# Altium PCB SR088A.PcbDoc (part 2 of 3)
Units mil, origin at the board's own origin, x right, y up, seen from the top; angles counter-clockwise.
Board outline 5010 x 3800 mil, 6 copper layers (Top Layer, Signal Layer 1, Signal Layer 2, Signal Layer 3, Signal Layer 4, Bottom Layer), stack 61.4 mil thick; 199 components, 82 nets, 478 pads, 1347 vias.
Unrouted connection lines stored in the file: 13.
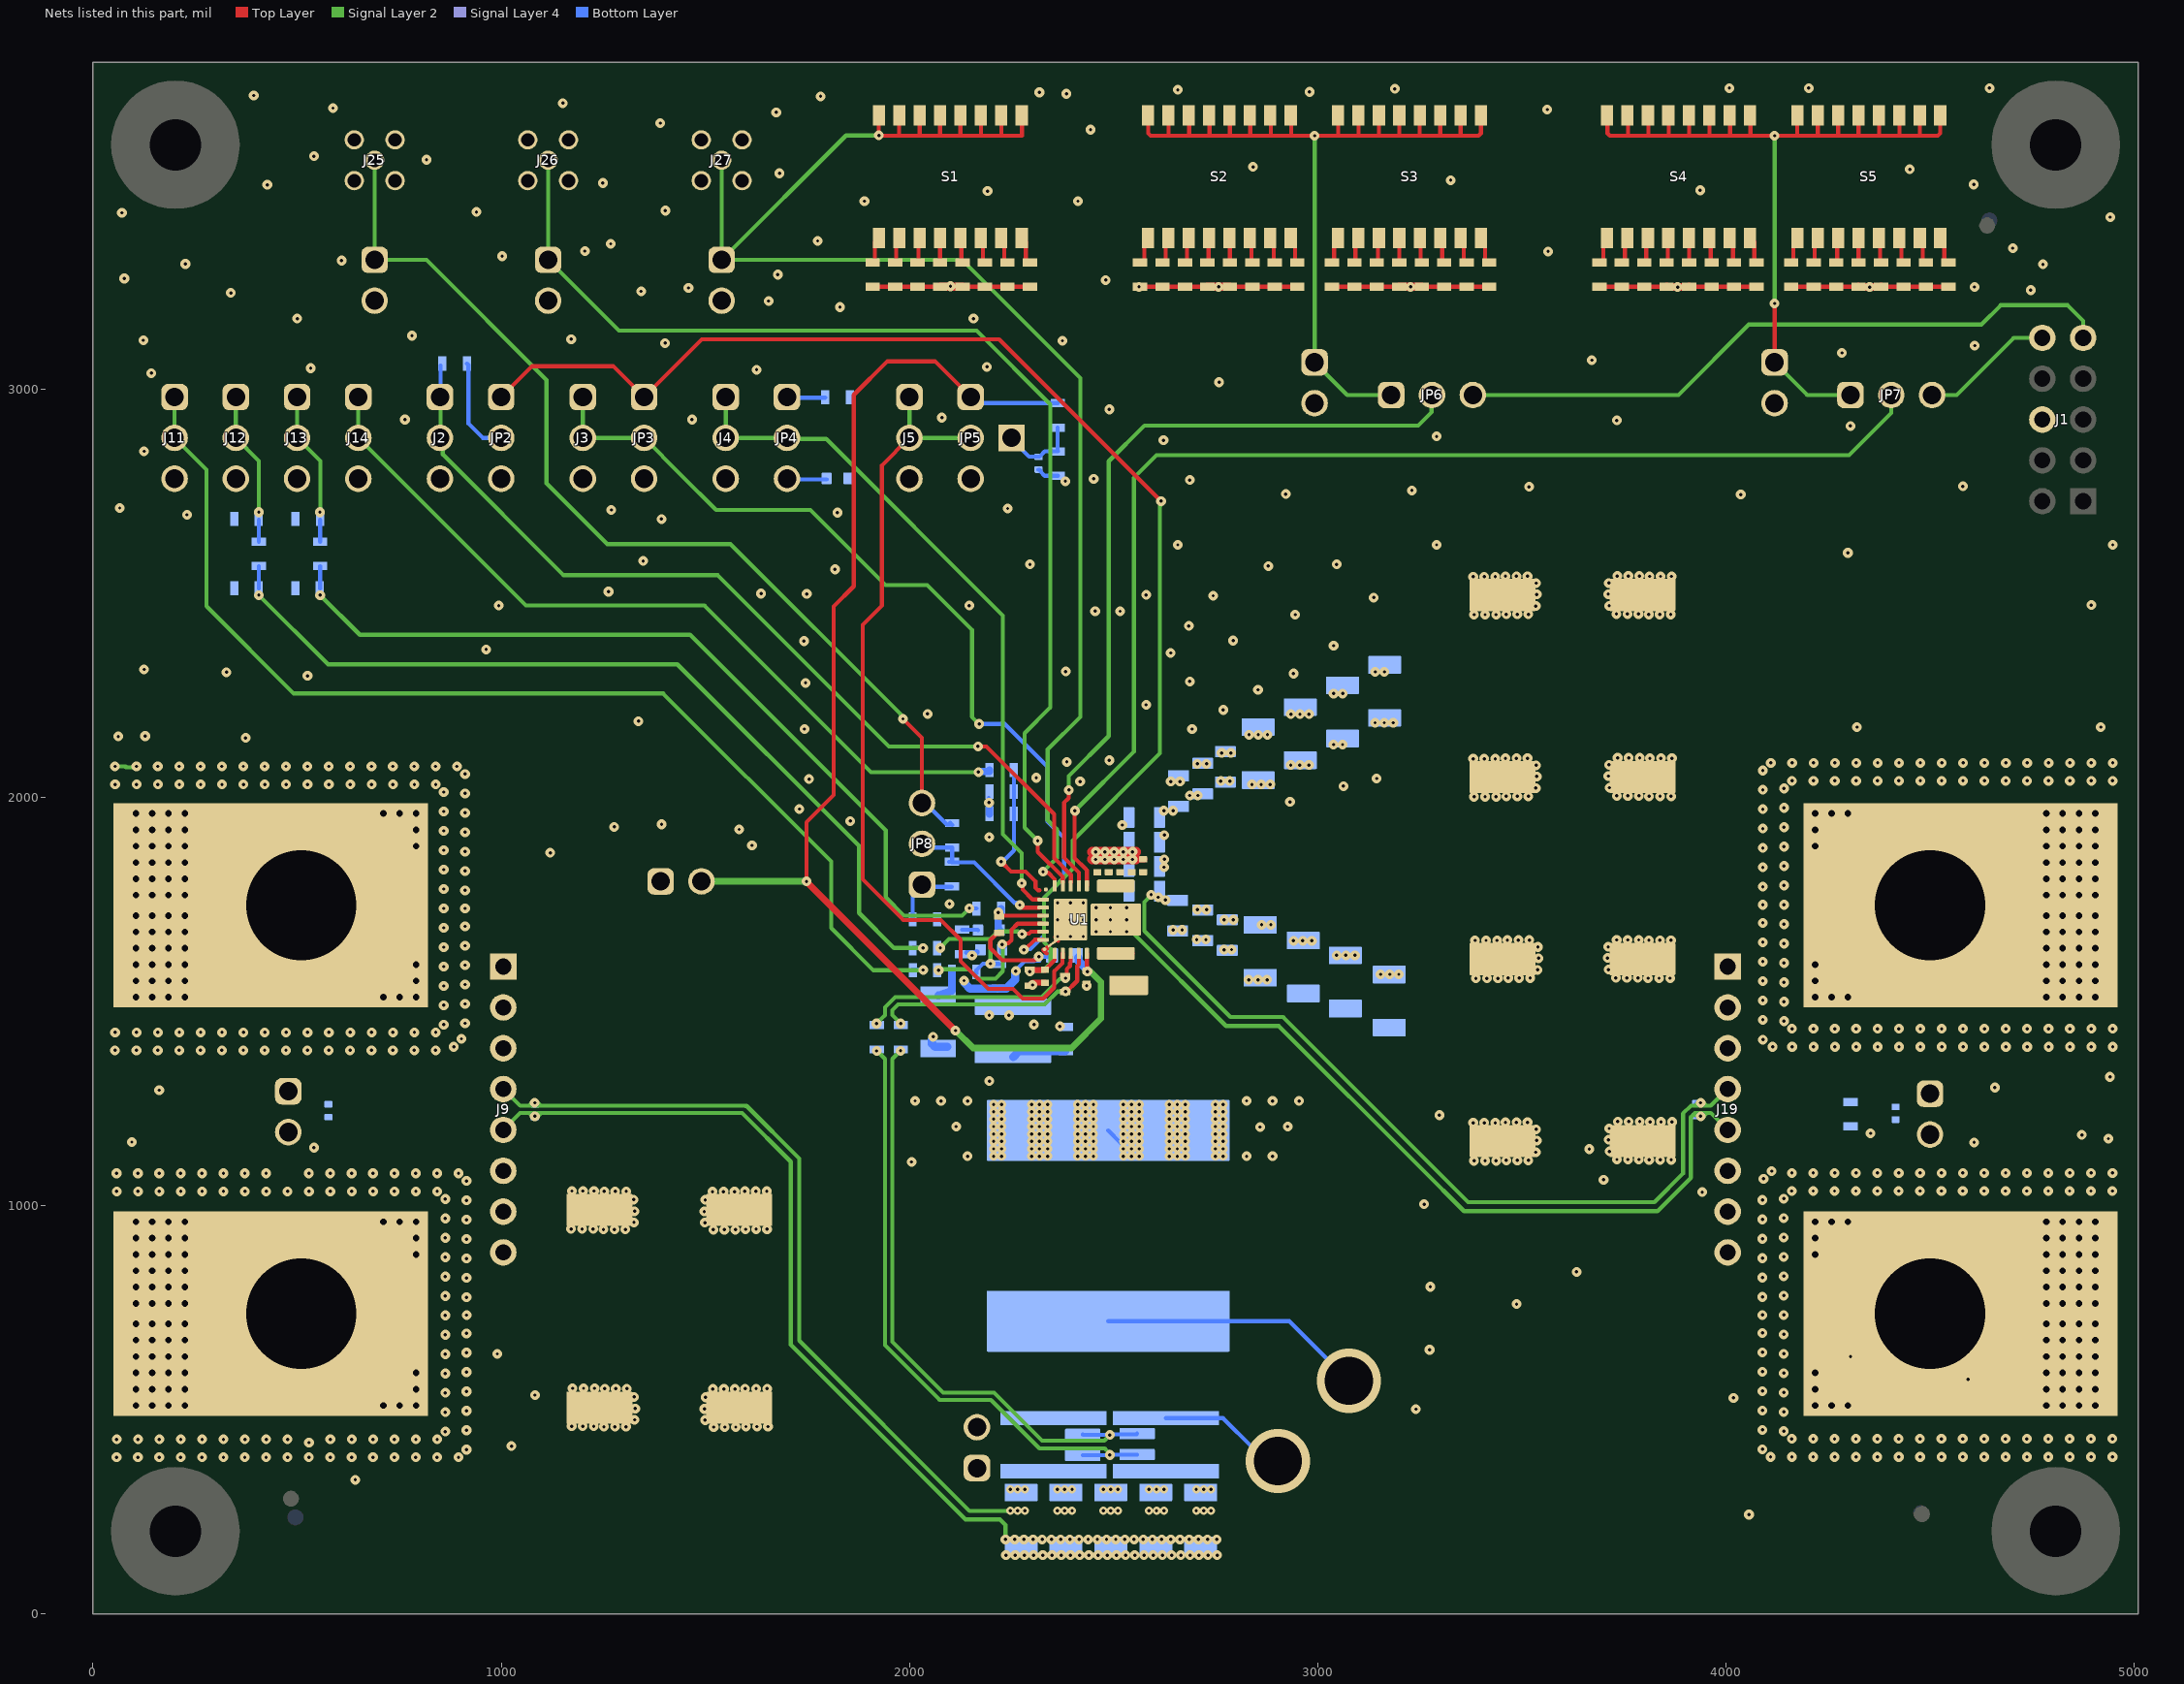
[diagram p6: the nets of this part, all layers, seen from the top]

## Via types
v1: diameter 24, hole 8, Top Layer to Bottom Layer, tented both sides, 935 vias

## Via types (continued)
v2: diameter 32, hole 16, Top Layer to Bottom Layer, 232 vias
v3: diameter 22, hole 8, Top Layer to Bottom Layer, tented both sides, 128 vias
v4: diameter 20, hole 8, Top Layer to Bottom Layer, tented both sides, 30 vias
v5: diameter 19.68, hole 7.87, Top Layer to Bottom Layer, tented both sides, 18 vias
v6: diameter 157.48, hole 118.11, Top Layer to Bottom Layer, 2 vias
v7: diameter 150, hole 125.98, Top Layer to Bottom Layer, 2 vias

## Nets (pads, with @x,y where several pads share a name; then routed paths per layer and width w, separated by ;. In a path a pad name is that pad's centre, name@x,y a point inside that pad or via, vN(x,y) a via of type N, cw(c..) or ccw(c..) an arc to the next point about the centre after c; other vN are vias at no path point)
AGND: C1.2 C2.2 C6.1 C7.1 C8.2 C10.2 C50.1 C51.1 C52.2 C53.2 C54.2 C55.2 J1.6 J2.3 J3.3 J4.3 J5.3 J6.2 J7.2 J11.3 J12.3 J13.3 J14.3 J15.2 J16.2 J17.2 J25.2 J25.3 J25.4 J25.5 J26.2 J26.3 J26.4 J26.5 J27.2 J27.3 J27.4 J27.5 JP2.3 JP3.3 JP5.3 NT1.2 R7.1 R9.1 R11.1 R13.2 R15.2 R16.1 R17.1 R18.1 R19.2 R20.1 R21.1 R22.1 R23.2 R24.2 R25.1 R26.2 R27.1 R28.2 R29.1 R30.1 R31.1 R32.1 R33.1 R34.1 R35.2 R36.1 R37.1 R38.1 R39.2 R40.2 R41.1 R42.2 R43.1 R44.2 R45.1 R46.1 R47.1 R48.1 R49.1 R50.1 R51.2 R52.1 R53.1 R54.1 R55.2 R60.1 U1.1 | length 2626.8
  Top Layer w6: U1.1@2333.63,1629.09 NT1.2@2345.16,1637.81
  Top Layer w10: R16.1@1910,3250 R17.1@1965,3250 R18.1@2020,3250 R19.2@2075,3250 ; R20.1@2130,3250 R21.1@2185,3250 R22.1@2240,3250 R23.2@2295,3250 ; C10.2@2220.47,1664.74 2212.86,1664.74 2198.39,1650.27 2198.39,1630.08 2227.84,1600.62 2307.92,1600.62 v1(2316.8,1609.5) ; U1.1@2334.25,1628.49 2338.2,1632.45 ; 2336.1,1628.15 2336.18,1628.23 ; 2336.26,1617.32 U1.1@2327.56,1626.02 ; R24.2@2565,3250 R25.1@2620,3250 R26.2@2675,3250 R27.1@2730,3250 ; R28.2@2785,3250 R29.1@2840,3250 R30.1@2895,3250 R31.1@2950,3250 ; R32.1@3035,3250 R33.1@3090,3250 R34.1@3145,3250 R35.2@3200,3250 ; R36.1@3255,3250 R37.1@3310,3250 R38.1@3365,3250 R39.2@3420,3250 ; R40.2@3690,3250 R41.1@3745,3250 R42.2@3800,3250 R43.1@3855,3250 ; R44.2@3910,3250 R45.1@3965,3250 R46.1@4020,3250 R47.1@4075,3250 ; R48.1@4160,3250 R49.1@4215,3250 R50.1@4270,3250 R51.2@4325,3250 ; R52.1@4380,3250 R53.1@4435,3250 R54.1@4490,3250 R55.2@4545,3250 ; U1.1@2327.56,1626.02 2327.91,1626.11 2329.13,1626.42 U1.1@2327.56,1626.02
  Top Layer w19.5: R19.2@2075,3250 R20.1@2130,3250 ; R27.1@2730,3250 R28.2@2785,3250 ; R35.2@3200,3250 R36.1@3255,3250 ; R43.1@3855,3250 3855.25,3249.75 3881.35,3249.75 v1(3881.79,3249.31) 3882.24,3249.75 3909.75,3249.75 R44.2@3910,3250 ; R51.2@4325,3250 4325.25,3249.75 4351.71,3249.75 v1(4352.21,3249.26) 4352.7,3249.75 4379.75,3249.75 R52.1@4380,3250
  Bottom Layer w10: v1@2152.75,1609.7 2153.16,1609.3 2156.61,1609.3 C6.1@2164.46,1617.14 ; R7.1@2194.26,1997.6 2194.26,1987.48 v1(2194.95,1986.79) ; v1(2260.64,1574.06) 2260.64,1576.87 2281.82,1598.06 2305.36,1598.06 2307.19,1599.89 v1@2318.66,1599.89 ; 2303.4,1599.89 2313.01,1609.5 2346.18,1609.5 C1.2@2349.21,1612.53 ; C51.1@2316.23,2802.09 2318.2,2802.09 2321.08,2799.22 2321.08,2797.25 2331.32,2787.01 R15.2@2363.46,2787.01
  Bottom Layer w12: R9.1@2139.67,1619.58 C6.1@2165.96,1619.58
  Bottom Layer w14: v1@2152.75,1609.7 C6.1@2164.46,1621.24
  Bottom Layer w18: C7.1@2195.76,1958.82 v1@2195.76,1985.98
  Bottom Layer w20: C8.2@2055.25,1405.88 2055.25,1396.06 2062.95,1388.36 C8.2@2092.79,1388.36 ; v1(2133.75,1550.48) 2133.75,1549.4 2135.92,1547.23 2135.92,1543.57 2148.43,1531.06 R60.1@2211.91,1531.06 ; R60.1@2219.41,1531.06 2237.5,1531.06 2258.76,1552.32 2258.76,1569.36 2259.87,1570.46 2259.87,1573.29 v1(2260.64,1574.06)
  other v1: 2057.97,1413.36 2305.04,1443.21 2434.18,1538.24 2153.38,1612.48 2098.18,1738.59 2195.63,1902.13 1582.79,1921.11 1392.85,1933.57 1855.21,1941.54 1730.3,1970.97 2418.14,2038.2 1754.21,2044.11 2310.81,2047.43 2385.39,2086.44 2489.54,2090.34 1742.85,2166.88 1336.32,2186.01 2044.36,2203.82 2579.72,2226.19 1745.44,2279.86 525.61,2297.08 2382.73,2307.83 2639.98,2353.15 962.99,2361.97 1741.62,2382.44 2516.15,2455.43 2454.84,2455.66 993.91,2469.25 2146.6,2469.25 2579.72,2495.39 1748.4,2497.66 1636.7,2498.66 1263,2503.31 1817.55,2557.97 2295.11,2570.15 1347.93,2578.51 2657.26,2618.11 1392.49,2681.16 230.3,2691.59 1823.7,2696.85 1269.88,2703.43 2240.63,2707.05 65.55,2708.16 4036.47,2741.1 2921.88,2742.37 3230.71,2751.27 3517.94,2760.17 4580.42,2761.44 2381.97,2773.7 2686.76,2776.69 2451.45,2779.77 125.12,2847.16 2622.44,2874.18 3291.47,2883.63 4305,2909.18 3732.72,2922.84 764.28,2924.99 1467.42,2924.99 2079.6,2929.73 2489.64,2949.82 2758.7,3016.38 142.93,3038.47 1625.52,3047.04 533.34,3050.76 2189.98,3053.97 3671.72,3070.27 4284.3,3088.06 4609.65,3105.85 1401.65,3112.1 2374.65,3117.83 123.25,3118.93 1171.53,3121.65 781.44,3130.38 500.31,3172.19 2156.94,3172.26 1829.68,3200.4 1655,3215.26 337.64,3234.97 1342.67,3239.07 4746.74,3241.82 1458.71,3247.28 2562.5,3250 2757.5,3250 3227.5,3250 4608.99,3249.75 2100.5,3251.48 2480.68,3266.56 76.79,3270.48 1677.61,3279.91 4776.66,3305.22 226.49,3305.96 608.91,3314.21 1002.36,3325.02 3564.4,3336.5 1205,3337.42 4702.69,3344.7 1268.11,3355.16 1775.34,3362.39 4941.3,3420.52 70.77,3431.37 939.26,3433.46 1402.24,3436.6 1889.76,3459.67 2412.84,3459.67 2191.31,3484.5 3936.79,3486.41 427.17,3499.83 4607.1,3500.73 1249.01,3504.17 3325.68,3511.23 1681.73,3528 4450.5,3537.97 2841.57,3543.7 816.93,3561.24 541.34,3569.83 2443.54,3635 1389.56,3651 1673.61,3677.47 3562.49,3684.06 588.04,3687.62 1150.94,3699.91 1782.35,3716.59 393.7,3718.68 2384.49,3722.84 2318.48,3726.43 2979.88,3727.56 2657.48,3732.45 3188.98,3735.01 4008.36,3736.69 4202.76,3736.69 4645.67,3736.69
ATRK: JP8.2 R58.1 R59.2 U1.17 | length 381.7
  Top Layer w10: v1(2270.2,1735.78) 2276.46,1729.53 U1.17@2318.62,1729.53
  Bottom Layer w10: JP8.2@2030.69,1885.7 2039.92,1876.46 R59.2@2104.86,1876.46 2104.86,1841.41 R58.1@2096.99,1841.41 ; R58.1@2103.67,1840.21 2158.49,1840.21 2257.47,1741.23 2260.97,1741.23 2266.42,1735.78 v1(2270.2,1735.78)
ATRK_EXT: J15.1 J25.1 JP8.3 R59.1 | length 2499.2
  Top Layer w10: v1(1984.31,2191.81) 2030.69,2145.43 JP8.3@2030.69,1985.7
  Signal Layer 2 w10: J15.1@690,3295 J25.1@690,3560 ; J15.1@690,3316 816.75,3316 1111.02,3021.73 1111.02,2768.6 1259.71,2619.91 1561.67,2619.91 1977.95,2203.63 1977.95,2201.96 1984.31,2195.6 v1(1984.31,2191.81)
  Bottom Layer w10: JP8.3@2030.69,1985.7 2038.71,1985.7 2091.66,1932.75 R59.1@2099.16,1932.75 ; R59.1@2099.92,1936.9 R59.1@2104.92,1931.9
BIAS: C1.1 C2.1 JP1.2 JP5.1 R14.2 U1.6 | length 3211.5
  Top Layer w10: v1@1747.8,1793.21 1747.8,1938.45 1814.55,2005.19 1814.55,2467.32 1863.62,2516.4 1863.62,2985.34 1945.86,3067.58 2062.42,3067.58 JP5.1@2150,2980 ; U1.6@2434.68,1617.32 2434.68,1582.08 2437.56,1579.21 C2.1@2437.85,1579.21
  Top Layer w16: v1@1747.8,1793.21 v1(2112.61,1428.4) ; C2.1@2437.39,1576.42 C2.1@2437.85,1576.89
  Signal Layer 2 w16: JP1.2@1490.54,1793.81 v1@1748.4,1793.81 ; v1@2112.89,1428.69 2155.86,1385.72 2397.07,1385.72 2469.06,1457.71 2469.06,1547.33 2445.04,1571.36 2437.35,1571.36 v1(2435.82,1572.89)
  Bottom Layer w10: JP5.1@2150,2980 2164.84,2965.16 R14.2@2363.46,2965.16
  Bottom Layer w20: C1.1@2412.74,1607.07 2414.99,1604.81 2414.99,1597.48 2435.05,1577.42 2435.05,1573.65 v1(2435.82,1572.89)
  other v1: 1747.8,1793.81
CFG1: JP6.2 U1.11 | length 1983.3
  Top Layer w10: v1@2390.34,2014.74 2390.34,1997.77 2378.7,1986.13 2378.7,1851.96 2415,1815.66 U1.11@2415,1782.68
  Signal Layer 2 w10: v1@2390.34,2014.74 2390.34,2051.75 2488.13,2149.54 2488.13,2822.66 2575.77,2910.3 3246.03,2910.3 3279.11,2943.38 3279.11,2984.11 JP6.2@3280,2985
  other v1: 2390.55,2017.46
CFG2: JP7.2 U1.10 | length 3057.6
  Top Layer w10: v1@2404.73,1966.86 2404.73,1851.2 2432.87,1823.06 2434.68,1820.5 U1.10@2434.68,1782.68
  Signal Layer 2 w10: v1(2405.19,1966.86) 2549.72,2111.39 2549.72,2782.15 2605.1,2837.52 4301.83,2837.52 4405,2940.69 JP7.2@4405,3005.77
COMP: C9.2 C10.1 R56.1 U1.18 | length 168.8
  Top Layer w10: C10.1@2218.85,1708.24 C10.1@2219.86,1707.24 ; C10.1@2226.86,1709.74 2232.61,1709.74 2232.72,1709.84 U1.18@2327.4,1709.84
  Top Layer w16: v1(2217.85,1717.76) 2218.85,1716.76 C10.1@2218.85,1708.24
  Bottom Layer w18: R56.1@2217.52,1717.43 2217.52,1677.85 C9.2@2221.03,1674.34 ; R56.1@2220.62,1717.76 2220.62,1718.91 2223.11,1718.91 2224.11,1719.91 R56.1@2224.11,1727.2
COMP_J: C53.1 R56.2 R62.1 | length 2091.1
  Signal Layer 2 w10: v1(556.59,2494.96) 653.82,2397.73 1462.52,2397.73 1941.87,1918.39 1941.87,1754.37 1986.6,1709.64 2128.72,1709.64 v1(2146.78,1727.7)
  Bottom Layer w10: R62.1@556.33,2565.95 556.4,2565.87 C53.1@556.4,2511.47 ; v1(2146.78,1727.7) 2163.6,1727.7 R56.2@2164.11,1727.2
CSA: C5.2 R5.1 U1.4 | length 580.2
  Top Layer w10: C5.2@2381.19,1562.43 2383.06,1562.43 2385.56,1564.93 2385.56,1578.78 2393.08,1586.31 2393.08,1593.65 2395.24,1595.81 U1.4@2395.24,1608.54
  Signal Layer 2 w10: v1(1919.57,1445.5) 1940.06,1465.99 1940.06,1485.28 1965.15,1510.36 2323.74,1510.36 2367.34,1553.96 2375.66,1553.96 2382.13,1560.43 v1@2382.13,1562.7
  Bottom Layer w10: R5.1@1919.57,1442.03 v1(1919.57,1445.5)
  other v1: 2382.13,1556.64
CSB: C5.1 R6.1 U1.5 | length 590
  Top Layer w10: C5.1@2382.29,1521.34 C5.1@2383.5,1522.54 ; C5.1@2383.31,1523.6 2383,1523.03 C5.1@2383.5,1522.54 ; C5.1@2383.71,1522.33 C5.1@2383.5,1522.54 ; U1.5@2414.92,1608.54 2414.92,1590.21 2410.96,1586.25 2410.96,1573.65 ccw(c2435.82,1572.89) 2410.96,1572.13 2410.96,1550 C5.1@2383.5,1522.54
  Signal Layer 2 w10: v1(1978.47,1445.5) 1978.47,1445.83 1957.94,1466.37 1957.94,1477.87 1972.55,1492.49 2331.14,1492.49 2362.72,1524.06 v1(2382.46,1524.06)
  Bottom Layer w10: R6.1@1979.3,1442.03 R6.1@1979.3,1445.08
DIP1: J6.1 JP6.1 S2.9 S2.10 S2.11 S2.12 S2.13 S2.14 S2.15 S2.16 S3.9 S3.10 S3.11 S3.12 S3.13 S3.14 S3.15 S3.16 | length 2383.1
  Top Layer w10: S2.16@2585,3670 2585,3625.86 2590.86,3620 v1(2992.5,3620) 3394.14,3620 3400,3625.86 S3.9@3400,3670 ; 2635,3620.79 2635,3670 S2.15@2635,3670.79 ; 2685,3620.79 2685,3670 S2.14@2685,3670.79 ; 2735,3621.79 2735,3670 S2.13@2735,3671.57 ; 2785,3621.57 2785,3670 S2.12@2785,3671.57 ; 2835,3620.79 2835,3670 S2.11@2835,3671.57 ; 2885,3621.79 2885,3670 S2.10@2885,3671.57 ; 2935,3621.57 2935,3670 S2.9@2935,3671.57 ; 3050,3620.79 S3.16@3050,3670 S3.16@3050,3670.79 ; 3100,3620.79 S3.15@3100,3670 S3.15@3100,3670.79 ; 3150,3621.79 S3.14@3150,3670 S3.14@3150,3671.57 ; 3200,3621.57 S3.13@3200,3670 S3.13@3200,3671.57 ; 3250,3620.79 S3.12@3250,3670 S3.12@3250,3671.57 ; 3300,3621.79 S3.11@3300,3670 S3.11@3300,3671.57 ; 3350,3621.57 S3.10@3350,3670 S3.10@3350,3671.57
  Signal Layer 2 w10: J6.1@2989.98,3067.45 3072.43,2985 JP6.1@3180,2985 ; J6.1@2992.5,3069.98 v1(2992.5,3620)
DIP2: J7.1 JP7.1 S4.9 S4.10 S4.11 S4.12 S4.13 S4.14 S4.15 S4.16 S5.9 S5.10 S5.11 S5.12 S5.13 S5.14 S5.15 S5.16 | length 2383
  Top Layer w10: S4.16@3710,3670 3710,3625.86 3715.86,3620 3760,3620 3810,3620 3860,3620 3910,3620 3960,3620 4010,3620 4119.13,3620 v1(4119.22,3619.91) 4119.32,3620 4225,3620 4275,3620 4325,3620 4375,3620 4425,3620 4475,3620 4519.14,3620 4525,3625.86 S5.9@4525,3670 ; 3760,3620.79 3760,3670 S4.15@3760,3670.79 ; 3810,3620.79 3810,3670 S4.14@3810,3670.79 ; 3860,3621.79 3860,3670 S4.13@3860,3671.57 ; 3910,3621.57 3910,3670 S4.12@3910,3671.57 ; 3960,3620.79 3960,3670 S4.11@3960,3671.57 ; 4010,3621.79 4010,3670 S4.10@4010,3671.57 ; 4060,3621.57 4060,3670 S4.9@4060,3671.57 ; J7.1@4119.22,3085 v1(4119.22,3209.39) ; 4175,3620.79 S5.16@4175,3670 S5.16@4175,3670.79 ; 4225,3620.79 S5.15@4225,3670 S5.15@4225,3670.79 ; 4275,3621.79 S5.14@4275,3670 S5.14@4275,3671.57 ; 4325,3621.57 S5.13@4325,3670 S5.13@4325,3671.57 ; 4375,3620.79 S5.12@4375,3670 S5.12@4375,3671.57 ; 4425,3621.79 S5.11@4425,3670 S5.11@4425,3671.57 ; 4475,3621.57 S5.10@4475,3670 S5.10@4475,3671.57
  Signal Layer 2 w10: J7.1@4106.6,3077.62 4199.22,2985 JP7.1@4305,2985 ; v1(4119.22,3209.39) v1(4119.22,3619.91)
  Signal Layer 4 w10: v1@4117.5,3211.11 v1(4119.22,3209.39)
DLY: J4.1 J4.2 JP4.2 U1.16 | length 1699.4
  Top Layer w10: v1@2273.71,1786.75 2277.44,1783.02 2277.44,1773.65 2301.8,1749.29 U1.16@2318.62,1749.29
  Signal Layer 2 w10: J4.1@1550,2980 J4.2@1550,2880 JP4.2@1700,2880 1702.71,2877.29 1796.16,2877.29 2228.64,2444.82 2228.64,1909.24 2275.03,1862.84 v1(2275.03,1789.42)
IMON: R8.2 R60.2 R61.1 U1.20 | length 395.4
  Top Layer w10: v1(2276,1664.61) 2277.16,1665.76 2293.04,1665.76 2297.67,1670.39 U1.20@2318.62,1670.39
  Signal Layer 2 w10: v1(2075.66,1630.83) 2097.25,1652.43 2198.39,1652.43 ; v1(2198.39,1592.27) 2198.39,1652.43 ; v1(2276,1664.61) 2272.22,1664.61 2265.5,1671.33 2217.29,1671.33 2198.39,1652.43
  Bottom Layer w10: R8.2@2163.79,1568.48 2163.79,1575.98 2180.08,1592.27 v1(2198.39,1592.27) 2198.99,1591.66 2218.8,1591.66 R60.2@2219.41,1591.06
IMON_J: C55.1 R61.2 R63.1 | length 2161.5
  Signal Layer 2 w10: v1(406.27,2494.96) 575.89,2325.34 1431.59,2325.34 1876.59,1880.34 1876.59,1716.13 1962.16,1630.55 v1(2033.41,1630.55)
  Bottom Layer w10: C55.1@406.4,2511.47 R63.1@406.4,2565.95 ; R61.2@2007.95,1630.21 2008.3,1630.55 v1(2033.41,1630.55)
L1: J8.2 L1.1 R1.2 R2.2 R3.2 R4.2 R6.2 | length 2385.6
  Signal Layer 2 w10: v1@1974.16,1375.25 1957.88,1358.97 1957.88,666.35 2082.47,541.76 2207.1,541.76 2324.62,424.24 2477.45,424.24 v1(2490.94,437.72)
  Bottom Layer w10: R6.2@1978.08,1380.88 R6.2@1978.08,1382.03 ; R2.2@2424.48,439.24 2425.24,438.48 2490.17,438.48 v1(2490.94,437.72) 2492.52,439.31 2556.1,439.31 R1.2@2557.69,440.9 ; L1.1@2487,716.54 2930.55,716.54 v6(3076.45,570.64) ; R3.2@2628.16,478.96 2768.22,478.96 v6@2842.31,404.87
  other v1: 1978.19,1378.75
  other v6: 2902.31,374.01
MODE: J3.1 J3.2 JP3.2 U1.21 | length 2267.2
  Top Layer w10: v1(2280.51,1626.42) 2282.47,1626.42 2306.83,1650.79 U1.21@2327.4,1650.79
  Signal Layer 2 w10: J3.1@1200,2980 J3.2@1200,2880 JP3.2@1350,2880 1440.72,2789.28 1526.57,2703.43 1757.62,2703.43 1941.36,2519.69 2043.29,2519.69 2153.16,2409.82 2153.16,2196.94 v1(2170.75,2179.34)
  Bottom Layer w10: v1(2170.75,2179.34) 2233.23,2179.34 2338.6,2073.97 2338.6,1940.31 2379.1,1899.81 2379.1,1803.19 2329.41,1753.5 2329.41,1661.29 2296.62,1628.5 2283.83,1628.5 v1@2281.13,1625.8
NetC8_1: C8.1 R8.1 | length 81.2
  Bottom Layer w19.5: C8.1@2070.78,1514.33 2103.93,1526.23 2103.93,1534.6 2103.99,1564.43 R8.1@2104,1572.18
NetC9_1: C9.1 R9.2 | length 39.4
  Bottom Layer w10: R9.2@2129.01,1675.62 2129.65,1674.98 2167.24,1674.98 C9.1@2167.88,1674.34
NetC20_2: C20.2 R10.2 | length 132.5
  Bottom Layer w20: R10.2@2254.19,1363.52 2268.05,1377.37 C20.2@2381,1377.37
NetC50_2: C50.2 JP4.3 | length 96.7
  Bottom Layer w10: JP4.3@1700.48,2778.26 C50.2@1797.2,2778.26
NetC51_2: C51.2 JP9.1 R14.1 R15.1 | length 196.8
  Bottom Layer w10: JP9.1@2248.52,2878.7 2293.25,2833.97 2318.58,2833.97 2321.08,2836.46 2321.08,2836.64 2331.45,2847.01 R15.1@2363.46,2847.01 ; R15.1@2363.13,2847.34 R14.1@2363.13,2905.16
NetC52_1: C52.1 J13.1 J13.2 R62.2 | length 359.1
  Signal Layer 2 w10: J13.1@500,2980 J13.2@500,2880 556.73,2823.27 556.73,2699.03 v1(555.77,2698.07)
  Bottom Layer w10: R62.2@556.33,2625.95 C52.1@556.33,2679.25
NetC54_1: C54.1 J12.1 J12.2 R63.2 | length 356.8
  Signal Layer 2 w10: J12.1@350,2980 J12.2@350,2880 406.45,2823.55 406.45,2700.09 v1@406.27,2699.91
  Bottom Layer w10: R63.2@406.4,2625.95 C54.1@406.4,2679.25
  other v1: 406.27,2698.07
NetJP2_2: JP2.2 R12.1 | length 243.4
  Bottom Layer w10: R12.1@916.15,3062.08 920,3058.22 920,2914.55 954.55,2880 JP2.2@1000,2880
NetJP4_1: JP4.1 R13.1 | length 93.7
  Bottom Layer w10: JP4.1@1700.48,2978.26 1792.77,2978.26 R13.1@1793.77,2979.26
NetJP8_1: JP8.1 R11.2 R58.2 | length 169.2
  Bottom Layer w10: R11.2@2007.95,1701.13 2007.95,1756.88 2030.69,1779.62 JP8.1@2030.69,1785.7 2036.18,1780.21 R58.2@2103.67,1780.21
NetR16_2: R16.2 S1.1 | length 66.3
  Top Layer w10: R16.2@1910,3310 1910.23,3310 1915.23,3315 1915.23,3360.23 S1.1@1925,3370
NetR17_2: R17.2 S1.2 | length 64.1
  Top Layer w10: R17.2@1965,3310 1965,3312.52 1967.48,3315 1967.48,3362.48 S1.2@1975,3370
NetR18_2: R18.2 S1.3 | length 62.1
  Top Layer w10: R18.2@2020,3310 2022.49,3312.49 2022.49,3367.49 S1.3@2025,3370
NetR19_1: R19.1 S1.4 | length 60
  Top Layer w10: R19.1@2075,3310 S1.4@2075,3370
NetR20_2: R20.2 S1.5 | length 62.1
  Top Layer w10: S1.5@2125,3370 2127.38,3367.62 2127.38,3312.62 R20.2@2130,3310
NetR21_2: R21.2 S1.6 | length 64.1
  Top Layer w10: S1.6@2175,3370 2180,3365 2180,3315 R21.2@2185,3310
NetR22_2: R22.2 S1.7 | length 67.7
  Top Layer w10: S1.7@2225,3370 2232.5,3362.5 2232.5,3315 2237.5,3310 R22.2@2240,3310
NetR23_1: R23.1 S1.8 | length 71.3
  Top Layer w10: S1.8@2275,3370 2284.91,3360.09 2284.91,3315 2289.91,3310 R23.1@2295,3310
NetR24_1: R24.1 S2.1 | length 71.3
  Top Layer w10: R24.1@2565,3310 2570.09,3310 2575.09,3315 2575.09,3360.09 S2.1@2585,3370
NetR25_2: R25.2 S2.2 | length 67.7
  Top Layer w10: R25.2@2620,3310 2622.5,3310 2627.5,3315 2627.5,3362.5 S2.2@2635,3370
NetR26_1: R26.1 S2.3 | length 64.1
  Top Layer w10: R26.1@2675,3310 2680,3315 2680,3365 S2.3@2685,3370
NetR27_2: R27.2 S2.4 | length 62.1
  Top Layer w10: R27.2@2730,3310 2732.62,3312.62 2732.62,3367.62 S2.4@2735,3370
NetR28_1: R28.1 S2.5 | length 60
  Top Layer w10: R28.1@2785,3310 S2.5@2785,3370
NetR29_2: R29.2 S2.6 | length 62.1
  Top Layer w10: S2.6@2835,3370 2837.51,3367.49 2837.51,3312.49 R29.2@2840,3310
NetR30_2: R30.2 S2.7 | length 64.1
  Top Layer w10: S2.7@2885,3370 2892.52,3362.48 2892.52,3315 2895,3312.52 R30.2@2895,3310
NetR31_2: R31.2 S2.8 | length 66.3
  Top Layer w10: S2.8@2935,3370 2944.77,3360.23 2944.77,3315 2949.77,3310 R31.2@2950,3310
NetR32_2: R32.2 S3.1 | length 66.3
  Top Layer w10: R32.2@3035,3310 3035.23,3310 3040.23,3315 3040.23,3360.23 S3.1@3050,3370
NetR33_2: R33.2 S3.2 | length 64.1
  Top Layer w10: R33.2@3090,3310 3090,3312.52 3092.48,3315 3092.48,3362.48 S3.2@3100,3370
NetR34_2: R34.2 S3.3 | length 62.1
  Top Layer w10: R34.2@3145,3310 3147.49,3312.49 3147.49,3367.49 S3.3@3150,3370
NetR35_1: R35.1 S3.4 | length 60
  Top Layer w10: R35.1@3200,3310 S3.4@3200,3370
NetR36_2: R36.2 S3.5 | length 62.1
  Top Layer w10: S3.5@3250,3370 3252.38,3367.62 3252.38,3312.62 R36.2@3255,3310
NetR37_2: R37.2 S3.6 | length 64.1
  Top Layer w10: S3.6@3300,3370 3305,3365 3305,3315 R37.2@3310,3310
NetR38_2: R38.2 S3.7 | length 67.7
  Top Layer w10: S3.7@3350,3370 3357.5,3362.5 3357.5,3315 3362.5,3310 R38.2@3365,3310
NetR39_1: R39.1 S3.8 | length 71.3
  Top Layer w10: S3.8@3400,3370 3409.91,3360.09 3409.91,3315 3414.91,3310 R39.1@3420,3310
NetR40_1: R40.1 S4.1 | length 71.3
  Top Layer w10: R40.1@3690,3310 3695.09,3310 3700.09,3315 3700.09,3360.09 S4.1@3710,3370
NetR41_2: R41.2 S4.2 | length 67.7
  Top Layer w10: R41.2@3745,3310 3747.5,3310 3752.5,3315 3752.5,3362.5 S4.2@3760,3370
NetR42_1: R42.1 S4.3 | length 64.1
  Top Layer w10: R42.1@3800,3310 3805,3315 3805,3365 S4.3@3810,3370
NetR43_2: R43.2 S4.4 | length 62.1
  Top Layer w10: R43.2@3855,3310 3857.62,3312.62 3857.62,3367.62 S4.4@3860,3370
NetR44_1: R44.1 S4.5 | length 60
  Top Layer w10: R44.1@3910,3310 S4.5@3910,3370
NetR45_2: R45.2 S4.6 | length 62.1
  Top Layer w10: S4.6@3960,3370 3962.51,3367.49 3962.51,3312.49 R45.2@3965,3310
NetR46_2: R46.2 S4.7 | length 64.1
  Top Layer w10: S4.7@4010,3370 4017.52,3362.48 4017.52,3315 4020,3312.52 R46.2@4020,3310
NetR47_2: R47.2 S4.8 | length 66.3
  Top Layer w10: S4.8@4060,3370 4069.77,3360.23 4069.77,3315 4074.77,3310 R47.2@4075,3310
NetR48_2: R48.2 S5.1 | length 66.3
  Top Layer w10: R48.2@4160,3310.79 4160.23,3310.79 4165.23,3315.79 4165.23,3361.02 S5.1@4175,3370.79
NetR49_2: R49.2 S5.2 | length 64.1
  Top Layer w10: R49.2@4215,3310.79 4215,3313.31 4217.48,3315.79 4217.48,3363.27 S5.2@4225,3370.79
NetR50_2: R50.2 S5.3 | length 62.1
  Top Layer w10: R50.2@4270,3310.79 4272.49,3313.28 4272.49,3368.28 S5.3@4275,3370.79
NetR51_1: R51.1 S5.4 | length 60
  Top Layer w10: R51.1@4325,3310.79 S5.4@4325,3370.79
NetR52_2: R52.2 S5.5 | length 62.1
  Top Layer w10: S5.5@4375,3370.79 4377.38,3368.41 4377.38,3313.41 R52.2@4380,3310.79
NetR53_2: R53.2 S5.6 | length 64.1
  Top Layer w10: S5.6@4425,3370.79 4430,3365.79 4430,3315.79 R53.2@4435,3310.79
NetR54_2: R54.2 S5.7 | length 67.7
  Top Layer w10: S5.7@4475,3370.79 4482.5,3363.29 4482.5,3315.79 4487.5,3310.79 R54.2@4490,3310.79
NetR55_1: R55.1 S5.8 | length 71.3
  Top Layer w10: S5.8@4525,3370.79 4534.91,3360.88 4534.91,3315.79 4539.91,3310.79 R55.1@4545,3310.79
PGND: C3.1 C4.2 C11.1 C12.1 C13.1 C14.1 C15.1 C16.1 C17.1 C18.1 C19.1 C21.1 C22.1 C23.1 C24.1 C25.1 C26.1 C27.1 C28.1 C29.1 C30.1 C31.1 C32.1 C33.1 C34.1 C35.1 C36.1 C37.1 C38.1 C39.1 C40.1 C41.1 C42.1 C43.1 C44.1 C45.1 C46.1 C47.1 C48.1 C49.1 J9.5 J9.6 J9.7 J9.8 J10.2 J19.5 J19.6 J19.7 J19.8 J20.2 J22.1 J24.1 NT1.1 R10.1 R65.1 T2.1 T4.1 U1.8 U1.22 | length 4407.7
  Top Layer w6: NT1.1@2356.34,1646.24 U1.22@2367.88,1654.96
  Top Layer w10: U1.22@2356.77,1657.87 2364.1,1648.21 ; U1.22@2392.36,1658.66 U1.22@2392.84,1658.66 ; J20.2@4500,1173.71 J20.2@4514.87,1173.71
  Top Layer w14: C4.2@2294.67,1537.82 2299.17,1537.82 2299.67,1538.32 2299.67,1542.83 2302.34,1545.51 C3.1@2331.85,1545.51 ; C4.2@2294.67,1539.82 C4.2@2297.17,1542.32
  Top Layer w15.8: v1@2557.94,1847.77 C25.1@2574.23,1847.77
  Top Layer w25: v1@2447.24,1866.25 v1@2554.24,1866.25 ; v1@2447.3,1847.97 2456.51,1847.97 2460.11,1847.97 2479.06,1847.97 2488.2,1847.97 2501.65,1847.97 2516.29,1847.97 2524.14,1847.97 2546.73,1847.97 v1@2554.3,1847.97
  Signal Layer 2 w10: J9.5@1005,1185 1046.36,1226.36 1590.33,1226.36 1709.37,1107.32 1709.37,659.11 2137.44,231.03 2221.35,231.03 2235.37,217.01 v1(2235.37,182.05) ; 1068.9,1226.17 v1@1077.95,1217.12 ; v1@1079.27,1217.31 v1@1083.06,1217.31 ; v1@1080.74,1216.7 1088.32,1216.7 1097.97,1226.36 ; v5@2525.24,1729.53 2534.69,1729.53 2551.91,1712.32 2551.91,1663.3 2775.55,1439.65 2904.73,1439.65 3253.36,1091.02 3358.32,986.06 3832.33,986.06 3914.13,1067.86 3914.13,1216.22 3924.24,1226.34 ; 3921.02,1221.98 v1@3931.79,1221.98 ; 3924.06,1225.46 v1@3932.97,1216.55 ; 3924.63,1226.42 3938.23,1226.38 3957.82,1226.32 ; v1@3943.44,1216.55 3952.35,1225.46 ; 3957.82,1226.34 3962.99,1226.34 J19.5@4004.33,1185
  Signal Layer 4 w10: J9.5@1007,1185 1020.27,1185 J9.5@1020.27,1187
  Bottom Layer w10: C31.1@2548.27,1847.46 v1@2552.84,1842.89 ; C49.1@3926.95,1218.65 3937.93,1218.65 v1(3938.2,1218.38)
  other v1: 2236.53,143.43 2259.07,143.43 2281.61,143.43 2304.16,143.43 2326.7,143.43 2349.24,143.43 2371.78,143.43 2394.32,143.43 2416.87,143.43 2439.41,143.43 2461.95,143.43 2484.49,143.43 2507.03,143.43 2529.58,143.43 2552.12,143.43 2574.66,143.43 2597.2,143.43 2619.74,143.43 2642.29,143.43 2664.83,143.43 2687.37,143.43 2708.86,143.43 2731.35,143.43 2753.85,143.43 2257.87,182.05 2280.36,182.05 2302.85,182.05 2325.34,182.05 2347.83,182.05 2370.33,182.05 2392.82,182.05 2415.31,182.05 2437.8,182.05 2460.29,182.05 2482.79,182.05 2505.28,182.05 2527.77,182.05 2550.26,182.05 2572.75,182.05 2595.25,182.05 2617.74,182.05 2640.23,182.05 2662.72,182.05 2685.21,182.05 2707.71,182.05 2730.2,182.05 2752.69,182.05 4056.64,242.89 642.56,328.15 57.72,383.14 110.07,383.14 162.42,383.14 214.77,383.14 267.12,383.14 319.47,383.14 371.82,383.14 424.17,383.14 476.52,383.14 528.87,383.14 581.22,383.14 633.57,383.14 685.92,383.14 738.27,383.14 790.62,383.14 842.97,383.14 895.32,383.14 4109.28,384.06 4161.63,384.06 4213.98,384.06 4266.33,384.06 4318.68,384.06 4371.03,384.06 4423.38,384.06 4475.73,384.06 4528.08,384.06 4580.43,384.06 4632.78,384.06 4685.13,384.06 4737.48,384.06 4789.83,384.06 4842.18,384.06 4894.53,384.06 4946.88,384.06 915,401.86 4089.6,402.78 1025.26,410.46 529.14,419.3 57.99,427.3 110.34,427.3 162.69,427.3 215.04,427.3 267.39,427.3 319.74,427.3 372.09,427.3 424.44,427.3 476.79,427.3 581.49,427.3 633.84,427.3 686.19,427.3 738.54,427.3 790.89,427.3 843.24,427.3 4161.36,428.23 4213.71,428.23 4266.06,428.23 4318.41,428.23 4370.76,428.23 4423.11,428.23 4475.46,428.23 4527.81,428.23 4580.16,428.23 4632.51,428.23 4684.86,428.23 4737.21,428.23 4789.56,428.23 4841.91,428.23 4894.26,428.23 4946.61,428.23 862.92,446.02 4141.68,446.95 915,449.34 4089.6,450.27 1251.67,458.12 1278.67,458.12 1305.67,458.12 1172.67,459.08 1199.67,459.08 1226.67,459.08 1326.63,475.12 862.92,493.51 4141.68,494.43 915,496.83 4089.6,497.75 3240.6,501.09 1328.08,502.6 4018.43,528.58 1325.63,531.12 1082.68,535.65 862.92,540.99 4141.68,541.92 915,544.31 4089.6,545.24 1253.71,551.16 1280.71,551.16 1307.71,551.16 1174.71,552.12 1201.71,552.12 1228.71,552.12 4593.07,573.93 862.92,588.48 4141.68,589.4 915,591.8 4089.6,592.72 4305.3,629.81 862.92,635.96 990.29,636.47 4141.68,636.89 915,639.28 4089.6,640.21 3274.13,646.4 862.92,683.44 4141.68,684.37 915,686.77 4089.6,687.69 862.92,730.93 915.22,731.39 4089.6,731.85 4141.68,731.85 3487.4,758.56 915,775.09 4089.6,776.02 862.92,778.41 4141.68,779.34 3275.83,800.78 915,822.58 4089.6,823.5 862.92,825.9 4141.68,826.82 3634.03,837.47 915,870.06 4089.6,870.99 862.92,873.38 4141.68,874.31 915,917.55 4089.6,918.47 862.92,920.87 4141.68,921.79 1250.31,941.39 1277.31,941.39 1304.31,941.39 1171.31,942.35 1198.31,942.35 1225.31,942.35 1325.28,958.39 915,965.03 4089.6,965.96 862.92,968.35 4141.68,969.28 1326.72,985.88 3260.75,1002.9 915,1012.52 4089.6,1013.44 1324.28,1014.39 862.92,1015.84 4141.68,1016.76 3942.1,1032.83 1252.35,1034.43 1279.35,1034.43 1306.35,1034.43 57.99,1034.56 110.34,1034.56 162.69,1034.56 215.04,1034.56 267.39,1034.56 319.74,1034.56 372.09,1034.56 424.44,1034.56 476.79,1034.56 529.14,1034.56 581.49,1034.56 633.84,1034.56 686.19,1034.56 738.54,1034.56 790.89,1034.56 843.24,1034.56 1173.35,1035.39 1200.35,1035.39 1227.35,1035.39 4161.36,1035.48 4213.71,1035.48 4266.06,1035.48 4318.41,1035.48 4370.76,1035.48 4423.11,1035.48 4475.46,1035.48 4527.81,1035.48 4580.16,1035.48 4632.51,1035.48 4684.86,1035.48 4737.21,1035.48 4789.56,1035.48 4841.91,1035.48 4894.26,1035.48 4946.61,1035.48 915,1060 3700.33,1063.12 4092.24,1065.44 57.72,1078.72 110.07,1078.72 162.42,1078.72 214.77,1078.72 267.12,1078.72 319.47,1078.72 371.82,1078.72 424.17,1078.72 528.87,1078.72 581.22,1078.72 633.57,1078.72 685.92,1078.72 738.27,1078.72 790.62,1078.72 842.97,1078.72 895.32,1078.72 4161.63,1079.65 4213.98,1079.65 4266.33,1079.65 4318.68,1079.65 4371.03,1079.65 4423.38,1079.65 4475.73,1079.65 4528.08,1079.65 4580.43,1079.65 4632.78,1079.65 4685.13,1079.65 4737.48,1079.65 4789.83,1079.65 4842.18,1079.65 4894.53,1079.65 4946.88,1079.65 4111.92,1084.16 2005.33,1106.5 3732.9,1112.49 3759.9,1112.49 3786.9,1112.49 3811.9,1111.53 3838.9,1111.53 3865.9,1111.53 2142.4,1120.65 2825.97,1120.65 2889.43,1120.65 3714.97,1132.53 3665.24,1138.1 541.34,1141.73 4608.06,1154.3 95.25,1155.29 3712.53,1161.05 4936.94,1163.58 4872.05,1172.86 4354.29,1176.66 3713.97,1188.53 2858.99,1192.03 2114.53,1193.15 2926.59,1193.15 3813.93,1204.57 3840.93,1204.57 3867.93,1204.57 3734.93,1205.53 3761.93,1205.53 3788.93,1205.53 1082.35,1218.41 3298.27,1221.14 2013.91,1256.17 2077.36,1256.02 2142.4,1256.02 2825.97,1256.17 2889.43,1256.02 2954.46,1256.02 162.42,1282.19 2195.77,1304.49 2195.41,1465.91 2243.86,1465.73 2301.55,1540.06 2831.15,1552.67 2853.74,1552.67 2876.23,1552.67 3809.43,1556.5 3836.43,1556.5 3863.43,1556.5 3730.43,1557.46 3757.43,1557.46 3784.43,1557.46 3712.51,1577.5 3710.06,1606.02 2770.67,1626.46 2788.98,1626.6 3711.51,1633.5 3732.47,1650.5 3759.47,1650.5 3786.47,1650.5 3811.47,1649.54 3838.47,1649.54 3865.47,1649.54 2703.67,1651.28 2726.15,1651.28 2645.64,1674.74 2668.12,1674.74 2456.51,1847.46 2479.06,1847.46 2501.65,1847.46 2524.14,1847.46 2546.73,1847.46 1120.06,1863.7 2456.51,1866.24 2479,1866.24 2501.6,1866.24 2524.08,1866.24 2546.68,1866.24 1614.27,1881.96 1276.82,1927.46 2521.5,1931.77 3811.69,2002.25 3838.69,2002.25 3865.69,2002.25 3732.69,2003.21 3759.69,2003.21 3786.69,2003.21 3714.77,2023.25 2640.13,2038.24 2662.61,2038.24 3712.33,2051.77 3713.77,2079.25 2705.08,2081.75 2727.56,2081.75 3813.73,2095.29 3840.73,2095.29 3867.73,2095.29 3734.73,2096.25 3761.73,2096.25 3788.73,2096.25 2764.73,2108.29 2787.32,2108.29 373.82,2145.21 61.88,2148.71 127.95,2149.57 2831.89,2152.93 2854.38,2152.93 2876.86,2152.93 2692.26,2166.88 2934.16,2203.46 2956.64,2203.46 2978.76,2203.46 2768.61,2213.81 3038.93,2253.72 3061.42,2253.72 2853.74,2263 2686.76,2283.46 2940.75,2302.73 326.91,2305.9 3140.8,2307.07 3163.29,2307.07 125.12,2312.99 3038.93,2371.05 2792.85,2383.44 2684.41,2419.34 2945.11,2447.06 3810.92,2447.64 3837.92,2447.64 3864.92,2447.64 3731.92,2448.6 3758.92,2448.6 3785.92,2448.6 3714,2468.64 4894.9,2470.47 3137.29,2488.89 2743.93,2493.37 3711.55,2497.15 3713,2524.64 3812.96,2540.68 3839.96,2540.68 3866.96,2540.68 3733.96,2541.64 3760.96,2541.64 3787.96,2541.64 2879.02,2565.96 3046.38,2570.15 4298.72,2598.43 3291.38,2618.11 4947.55,2618.11
  other v2: 105,510 145,510 185,510 225,510 711.27,510 751.27,510 791.27,510 4218.73,510 4258.73,510 4298.73,510 4785,510 4825,510 4865,510 4905,510 105,550 145,550 185,550 225,550 791.27,550 4218.73,550 4785,550 4825,550 4865,550 4905,550 105,590 145,590 185,590 225,590 791.27,590 4218.73,590 4785,590 4825,590 4865,590 4905,590 105,630 145,630 185,630 225,630 4785,630 4825,630 4865,630 4905,630 105,670 145,670 185,670 225,670 4785,670 4825,670 4865,670 4905,670 105,710 145,710 185,710 225,710 4785,710 4825,710 4865,710 4905,710 105,760 145,760 185,760 225,760 4785,760 4825,760 4865,760 4905,760 105,800 145,800 185,800 225,800 4785,800 4825,800 4865,800 4905,800 105,840 145,840 185,840 225,840 4785,840 4825,840 4865,840 4905,840 105,880 145,880 185,880 225,880 791.27,880 4218.73,880 4785,880 4825,880 4865,880 4905,880 105,920 145,920 185,920 225,920 791.27,920 4218.73,920 4785,920 4825,920 4865,920 4905,920 105,960 145,960 185,960 225,960 711.27,960 751.27,960 791.27,960 4218.73,960 4258.73,960 4298.73,960 4785,960 4825,960 4865,960 4905,960
  other v5: 2362.83,1658.66 2394.33,1658.66 2425.83,1658.66 2456.93,1670.47 2492.36,1670.47 2531.73,1670.47 2362.83,1700 2394.33,1700 2425.83,1700 2456.93,1700 2492.36,1700 2531.73,1700 2456.93,1729.53 2492.36,1729.53 2531.73,1729.53 2362.83,1741.34 2394.33,1741.34 2425.83,1741.34
PGOOD: J2.1 J2.2 R12.2 U1.12 | length 2266.9
  Top Layer w10: v1(2167.86,2124.35) 2188.46,2124.35 2354.36,1958.45 2354.36,1851.02 2395.31,1810.07 U1.12@2395.31,1791.46
  Signal Layer 2 w10: J2.2@850,2880 856.72,2873.28 856.72,2839.57 1152.7,2543.58 1530.41,2543.58 1949.64,2124.35 v1(2167.86,2124.35) ; J2.2@851.19,2880.04 J2.1@851.19,2980.04
  Bottom Layer w10: J2.1@851.19,2980.04 R12.2@851.19,3057.12
RT: C7.2 R7.2 R57.1 U1.15 | length 355.2
  Top Layer w10: v1(2224.57,1842.06) 2248.86,1817.77 2284.73,1817.77 2308.69,1793.81 2308.69,1778.44 2315.28,1771.85 2318.62,1771.85
  Bottom Layer w10: v1(2224.57,1842.06) 2228.36,1842.06 2255.76,1869.47 C7.2@2255.76,1958.82 R7.2@2255.76,2013.92 R57.1@2255.76,2049.95
RT_J: J14.1 J14.2 R57.2 | length 1988.7
  Signal Layer 2 w10: J14.2@650,2879.02 J14.1@650,2979.02 ; J14.2@650,2880 1060.75,2469.25 1497.81,2469.25 1905.68,2061.37 v1(2169.13,2061.37)
  Bottom Layer w18: v1(2169.13,2061.37) 2170.28,2062.52 2194.76,2062.52 2195.76,2063.52 R57.2@2195.76,2066.52
SCL: J1.9 JP6.3 | length 1643.7
  Signal Layer 2 w10: JP6.3@3380,2985 3883.64,2985 4056.15,3157.51 4625.57,3157.51 4672.97,3204.91 4836.88,3204.91 4875,3166.79 J1.9@4875,3125
SDA: J1.10 JP7.3 | length 337.5
  Signal Layer 2 w10: JP7.3@4505,2985 4565,2985 4705,3125 J1.10@4784.54,3125
SS: C6.2 R64.1 U1.19 | length 397.1
  Top Layer w10: v1(2227.26,1639.41) 2229.94,1642.09 2242.23,1642.09 2249.96,1649.82 2249.96,1675.12 2265,1690.16 U1.19@2327.4,1690.16
  Signal Layer 2 w10: v1(2071.49,1576.11) 2074.09,1578.71 2144.05,1578.71 2167.16,1555.6 2210.72,1555.6 2228.98,1573.85 2228.98,1637.7 v1(2227.26,1639.41)
  Bottom Layer w10: C6.2@2224.46,1621.24 2224.46,1628.74 2229.46,1633.74 C6.2@2234.03,1633.74
SS_J: J11.1 J11.2 R64.2 | length 2792.2
  Signal Layer 2 w10: J11.1@200,2980 J11.2@200,2880 277.84,2802.16 277.84,2467.92 491.82,2253.94 1396.84,2253.94 1808.41,1842.36 1808.41,1679.32 1911.76,1575.97 v1@2033.82,1575.97
  Bottom Layer w10: R64.2@2008.15,1575.97 2008.15,1577.27 v1@2033.82,1577.27
  other v1: 2033.82,1576.65
SW: C20.1 L1.2 TP1.1 U1.7 | length 125.3
  Top Layer w10: U1.7@2464.83,1617.27 2473.86,1617.26 2494.96,1617.22 2516.05,1617.22 2537.14,1617.29 U1.7@2546.89,1617.32
  Bottom Layer w10: L1.2@2487,1183.46 L1.2@2517.56,1152.91
  other v1: 2368.38,1438.63
  other v3: 2206.31,1120.65 2225.8,1120.65 2299.28,1120.65 2318.77,1120.65 2338.26,1120.65 2411.74,1120.65 2431.23,1120.65 2450.72,1120.65 2524.2,1120.65 2543.69,1120.65 2563.18,1120.65 2636.66,1120.65 2656.15,1120.65 2675.64,1120.65 2749.12,1120.65 2768.61,1120.65 2206.31,1138.77 2225.8,1138.77 2299.28,1138.77 2318.77,1138.77 2338.26,1138.77 2411.74,1138.77 2431.23,1138.77 2450.72,1138.77 2524.2,1138.77 2543.69,1138.77 2563.18,1138.77 2636.66,1138.77 2656.15,1138.77 2675.64,1138.77 2749.12,1138.77 2768.61,1138.77 2206.31,1156.9 2225.8,1156.9 2299.28,1156.9 2318.77,1156.9 2338.26,1156.9 2411.74,1156.9 2431.23,1156.9 2450.72,1156.9 2524.2,1156.9 2543.69,1156.9 2563.18,1156.9 2636.66,1156.9 2656.15,1156.9 2675.64,1156.9 2749.12,1156.9 2768.61,1156.9 2206.31,1175.02 2225.8,1175.02 2299.28,1175.02 2318.77,1175.02 2338.26,1175.02 2411.74,1175.02 2431.23,1175.02 2450.72,1175.02 2524.2,1175.02 2543.69,1175.02 2563.18,1175.02 2636.66,1175.02 2656.15,1175.02 2675.64,1175.02 2749.12,1175.02 2768.61,1175.02 2206.31,1193.15 2225.8,1193.15 2299.28,1193.15 2318.77,1193.15 2338.26,1193.15 2411.74,1193.15 2431.23,1193.15 2450.72,1193.15 2524.2,1193.15 2543.69,1193.15 2563.18,1193.15 2636.66,1193.15 2656.15,1193.15 2675.64,1193.15 2749.12,1193.15 2768.61,1193.15 2206.31,1211.27 2225.8,1211.27 2299.28,1211.27 2318.77,1211.27 2338.26,1211.27 2411.74,1211.27 2431.23,1211.27 2450.72,1211.27 2524.2,1211.27 2543.69,1211.27 2563.18,1211.27 2636.66,1211.27 2656.15,1211.27 2675.64,1211.27 2749.12,1211.27 2768.61,1211.27 2206.31,1229.4 2225.8,1229.4 2299.28,1229.4 2318.77,1229.4 2338.26,1229.4 2411.74,1229.4 2431.23,1229.4 2450.72,1229.4 2524.2,1229.4 2543.69,1229.4 2563.18,1229.4 2636.66,1229.4 2656.15,1229.4 2675.64,1229.4 2749.12,1229.4 2768.61,1229.4 2206.31,1247.52 2225.8,1247.52 2299.28,1247.52 2318.77,1247.52 2338.26,1247.52 2411.74,1247.52 2431.23,1247.52 2450.72,1247.52 2524.2,1247.52 2543.69,1247.52 2563.18,1247.52 2636.66,1247.52 2656.15,1247.52 2675.64,1247.52 2749.12,1247.52 2768.61,1247.52
SYNCIN: J16.1 J26.1 U1.13 | length 2881.1
  Top Layer w10: v1(2314.32,1893.11) 2314.32,1865.78 2375.55,1804.55 2375.55,1801.59 U1.13@2375.55,1791.46
  Signal Layer 2 w10: J16.1@1115,3290.99 J26.1@1115,3560 ; J16.1@1115,3316 1288.33,3142.67 2164.39,3142.67 2345.38,2961.67 2345.38,2219.86 2282.33,2156.81 2282.33,1925.1 v1(2314.32,1893.11)
SYNCOUT: J17.1 J27.1 S1.9 S1.10 S1.11 S1.12 S1.13 S1.14 S1.15 S1.16 U1.14 | length 3847.8
  Top Layer w10: S1.16@1925,3670.79 S1.16@1925,3670 v1(1925,3620.79) 1925.79,3620 1975,3620 2025,3620 2075,3620 2125,3620 2175,3620 2225,3620 2275.46,3620 2275.53,3620.07 S1.9@2275.53,3669.47 ; 1975,3620.79 S1.15@1975,3670 S1.15@1975,3670.79 ; 2025,3621.79 S1.14@2025,3670 S1.14@2025,3671.57 ; 2075,3621.57 S1.13@2075,3670 S1.13@2075,3671.57 ; 2125,3620.79 S1.12@2125,3670 S1.12@2125,3671.57 ; 2175,3621.79 S1.11@2175,3670 S1.11@2175,3671.57 ; 2225,3621.57 S1.10@2225,3670 S1.10@2225,3671.57 ; v1(2327.34,1817.53) 2330.02,1814.85 2339.98,1814.85 2355.94,1798.88 U1.14@2355.94,1782.68
  Signal Layer 2 w10: J17.1@1540,3291 J17.1@1540,3315.99 ; J27.1@1540,3561 J17.1@1540,3315.99 ; v1(1925,3620.79) 1844.79,3620.79 J17.1@1540,3315.99 ; v1(2327.34,1817.53) 2361.05,1851.24 2361.05,1921.47 2338.6,1943.93 2338.6,2116.75 2418.37,2196.52 2418.37,3026.25 2128.63,3315.99 J17.1@1540,3315.99
UVLO: J5.1 J5.2 JP5.2 U1.3 | length 2124.8
  Top Layer w10: J5.2@2000,2880 1932.68,2812.68 1932.68,2469.56 1885.43,2422.31 1885.43,1798.77 1984.98,1699.22 2076.91,1699.22 2125.3,1650.83 2125.3,1598.13 2192.94,1530.49 2253.86,1530.49 2277.49,1506.86 2327.98,1506.86 2354.57,1533.45 2354.57,1573.56 2374.6,1593.59 2374.6,1605.71 2375.55,1606.66 2375.55,1617.24 U1.3@2375.63,1617.32
  Signal Layer 2 w10: J5.1@2000,2980 J5.2@2000,2880 JP5.2@2150,2880 JP5.2@2171.59,2880
VCC: C3.2 C4.1 JP2.1 JP3.1 U1.2 | length 3292.7
  Top Layer w10: JP2.1@1000,2980 1075.69,3055.69 1274.31,3055.69 JP3.1@1350,2980 1491.65,3121.65 2219.97,3121.65 v1(2616.47,2725.15) ; C3.2@2332.64,1575.83 2336.69,1579.88 2336.69,1581.86 2355.94,1601.12 U1.2@2355.94,1608.54
  Top Layer w14: C4.1@2299.15,1577.32 2300.69,1577.32 2301.01,1577 C3.2@2331.85,1577
  Signal Layer 2 w10: v1@2295.36,1574.75 2327.26,1574.75 2335.84,1583.33 2345.5,1592.99 2345.5,1628.72 2329.41,1644.81 2329.41,1753.9 2400.34,1824.83 2400.34,1894.06 2613.53,2107.25 2613.53,2712.31 2613.79,2712.57 2613.79,2722.47 v1(2616.47,2725.15)
  other v1: 2294.94,1572.79
VIN: C11.2 C12.2 C13.2 C14.2 C15.2 C16.2 C17.2 C18.2 C19.2 J8.1 J9.1 J9.2 J9.3 J9.4 J10.1 J21.1 JP1.1 R1.1 R2.1 R3.1 R4.1 R5.2 T1.1 | length 3568.3
  Top Layer w10: J9.4@1004.87,1286.89 J9.4@1014.21,1277.54
  Signal Layer 2 w10: v1(54.09,2075.46) 80.24,2075.46 ; 80.24,2072.78 103.76,2072.78 v1(106.44,2075.46) ; J9.4@1006.47,1284.39 1046.63,1244.23 1104.31,1244.23 ; 1069.71,1246.04 v1@1073.78,1250.11 ; v1@1071.87,1246.8 1079.48,1246.8 1082.16,1249.48 1084.83,1246.8 v1@1092.45,1246.8 ; v1@1090,1251.21 1094.82,1246.38 ; 1095.01,1244.23 1597.73,1244.23 1598.35,1243.61 1601.37,1243.61 1730.2,1114.78 1730.2,669.11 2147.22,252.09 v4@2245.34,252.09 ; v1@1921.91,1376.96 1940.01,1358.87 1940.01,657.87 2073.99,523.89 2199.7,523.89 2318.41,405.17 2478.49,405.17 2489.62,394.04 v1@2489.62,388.86
  Bottom Layer w10: R5.2@1919.82,1375.28 R5.2@1920.22,1374.87 ; R5.2@1920.22,1378.64 R5.2@1920.22,1382.97 ; R2.1@2424.48,388.06 2424.88,388.46 2490.53,388.46 v1(2490.94,388.86) 2491.36,389.29 2557.27,389.29 R1.1@2557.69,389.72
  other v1: 1520.5,457.28 1547.5,457.28 1574.5,457.28 1599.5,458.24 1626.5,458.24 1653.5,458.24 1499.54,474.28 1498.09,501.76 1500.54,530.28 1518.46,550.32 1545.46,550.32 1572.46,550.32 1597.46,551.28 1624.46,551.28 1651.46,551.28 1519.73,940.75 1546.73,940.75 1573.73,940.75 1598.73,941.71 1624.57,941.99 1651.09,941.99 1498.77,957.75 1497.32,985.23 1499.77,1013.75 1517.69,1033.78 1544.69,1033.78 1571.69,1033.78 1596.69,1034.75 1623.69,1034.75 1650.69,1034.75 1082.23,1251.41 1919.7,1378.64 54.09,1379.88 106.44,1379.88 158.79,1379.88 211.14,1379.88 263.49,1379.88 315.84,1379.88 368.19,1379.88 420.54,1379.88 472.89,1379.88 525.24,1379.88 577.59,1379.88 629.94,1379.88 682.29,1379.88 734.64,1379.88 786.99,1379.88 839.34,1379.88 883.72,1388.45 902.44,1408.12 54.36,1424.04 106.71,1424.04 159.06,1424.04 211.41,1424.04 263.76,1424.04 316.11,1424.04 368.46,1424.04 420.81,1424.04 473.16,1424.04 525.51,1424.04 577.86,1424.04 630.21,1424.04 682.56,1424.04 734.91,1424.04 787.26,1424.04 839.61,1424.04 859.29,1442.76 911.37,1446.08 859.29,1490.24 911.37,1493.57 859.29,1537.73 911.37,1541.05 859.29,1585.21 911.37,1588.54 859.29,1632.7 911.37,1636.02 859.29,1680.18 911.37,1683.51 859.29,1727.67 911.37,1727.67 911.37,1771.83 859.29,1775.15 911.37,1819.32 859.29,1822.64 911.37,1866.8 859.29,1870.12 911.37,1914.28 859.29,1917.61 911.37,1961.77 859.29,1965.09 911.37,2009.25 859.29,2012.58 54.36,2031.3 106.71,2031.3 159.06,2031.3 211.41,2031.3 263.76,2031.3 316.11,2031.3 368.46,2031.3 420.81,2031.3 473.16,2031.3 525.51,2031.3 577.86,2031.3 630.21,2031.3 682.56,2031.3 734.91,2031.3 787.26,2031.3 839.61,2031.3 911.37,2056.74 158.79,2075.46 211.14,2075.46 263.49,2075.46 315.84,2075.46 368.19,2075.46 420.54,2075.46 472.89,2075.46 525.24,2075.46 577.59,2075.46 629.94,2075.46 682.29,2075.46 734.64,2075.46 786.99,2075.46 839.34,2075.46 891.69,2075.46
  other v2: 105,1510 145,1510 185,1510 225,1510 711.27,1510 751.27,1510 791.27,1510 105,1550 145,1550 185,1550 225,1550 791.27,1550 105,1590 145,1590 185,1590 225,1590 791.27,1590 105,1630 145,1630 185,1630 225,1630 105,1670 145,1670 185,1670 225,1670 105,1710 145,1710 185,1710 225,1710 105,1760 145,1760 185,1760 225,1760 105,1800 145,1800 185,1800 225,1800 105,1840 145,1840 185,1840 225,1840 105,1880 145,1880 185,1880 225,1880 791.27,1880 105,1920 145,1920 185,1920 225,1920 791.27,1920 105,1960 145,1960 185,1960 225,1960 711.27,1960 751.27,1960 791.27,1960
  other v4: 2246.74,252.09 2264.83,252.09 2282.92,252.09 2362.2,252.09 2380.29,252.09 2398.38,252.09 2474.66,252.09 2492.75,252.09 2510.84,252.09 2587.12,252.09 2605.21,252.09 2623.3,252.09 2702.58,252.09 2720.67,252.09 2738.76,252.09 2246.74,304.37 2264.83,304.37 2282.92,304.37 2362.2,304.37 2380.29,304.37 2398.38,304.37 2474.66,304.37 2492.75,304.37 2510.84,304.37 2587.12,304.37 2605.21,304.37 2623.3,304.37 2702.58,304.37 2720.67,304.37 2738.76,304.37
VOUT: C21.2 C22.2 C23.2 C24.2 C25.2 C26.2 C27.2 C28.2 C29.2 C30.2 C31.2 C32.2 C33.2 C34.2 C35.2 C36.2 C37.2 C38.2 C39.2 C40.2 C41.2 C42.2 C43.2 C44.2 C45.2 C46.2 C47.2 C48.2 C49.2 J19.1 J19.2 J19.3 J19.4 J20.1 J23.1 R65.2 T3.1 U1.9 | length 2143.3
  Top Layer w10: J23.1@4439.01,1674.01 J23.1@4500,1735
  Signal Layer 2 w10: v1@2592.72,1760.66 2575.31,1743.25 2575.31,1672.32 2786.19,1461.44 2915.38,1461.44 3368.75,1008.07 3825.01,1008.07 3894.88,1077.94 3894.88,1224.9 3914.36,1244.37 v1@3938.07,1244.37 ; 3916.12,1244.37 3938.07,1244.36 3951.93,1244.35 3958.86,1244.34 ; 3924.19,1244.55 v1@3933.1,1253.47 ; v1@3943.57,1253.47 3952.48,1244.55 ; 3960.85,1244.34 3962.85,1244.34 J19.4@4004.33,1285
  Bottom Layer w10: C49.2@3926.91,1250.27 3928.02,1251.38 v1(3938.07,1251.38)
  other v1: 3383.1,1109.49 3410.1,1109.49 3437.1,1109.49 3462.1,1110.45 3489.1,1110.45 3516.1,1110.45 3534.02,1130.49 3536.47,1159.01 3535.02,1186.49 3381.06,1202.53 3408.06,1202.53 3435.06,1202.53 3460.06,1203.49 3487.06,1203.49 3514.06,1203.49 4658.9,1288.89 4940.7,1315.08 4114.52,1388.63 4162.27,1388.58 4214.62,1388.58 4266.97,1388.58 4319.32,1388.58 4371.67,1388.58 4424.02,1388.58 4476.37,1388.58 4528.72,1388.58 4581.07,1388.58 4633.42,1388.58 4685.77,1388.58 4738.12,1388.58 4790.47,1388.58 4842.82,1388.58 4895.17,1388.58 4947.52,1388.58 4090.71,1405.99 4162,1432.74 4214.35,1432.74 4266.7,1432.74 4319.05,1432.74 4371.4,1432.74 4423.75,1432.74 4476.1,1432.74 4528.45,1432.74 4580.8,1432.74 4633.15,1432.74 4685.5,1432.74 4737.85,1432.74 4790.2,1432.74 4842.55,1432.74 4894.9,1432.74 4947.25,1432.74 4142.32,1451.46 4090.24,1454.78 4142.32,1498.95 4090.24,1502.27 4142.32,1546.43 4090.24,1549.75 3387.61,1556.18 3414.61,1556.18 3441.61,1556.18 3466.61,1557.14 3493.61,1557.14 3520.61,1557.14 3153.88,1566.11 3176.36,1566.11 3198.85,1566.11 3538.53,1577.18 4142.32,1593.92 4090.24,1597.24 3540.97,1605.7 3046.38,1612.79 3068.86,1612.79 3091.34,1612.79 3539.53,1633.18 4142.32,1641.4 4090.24,1644.72 2940.75,1648.3 2963.24,1648.3 2985.72,1648.3 3385.57,1649.22 3412.57,1649.22 3439.57,1649.22 3464.57,1650.18 3491.57,1650.18 3518.57,1650.18 2862.72,1687.6 2885.2,1687.6 4142.32,1688.89 4090.24,1692.21 2771.05,1699.7 2793.53,1699.7 2705.08,1724.54 2727.56,1724.54 4090.24,1736.37 4142.32,1736.37 2627.08,1748.01 2609.62,1754.82 2592.09,1761.14 4090.24,1780.53 4142.32,1783.85 4090.24,1828.02 2623.83,1828.61 4142.32,1831.34 2624.44,1847.67 4090.24,1875.5 4142.32,1878.82 2624.48,1907.15 4090.24,1922.99 4142.32,1926.31 2623.15,1966.86 2645.64,1966.86 4090.24,1970.47 4142.32,1973.79 2932.17,1988.48 3383.1,2001.2 3410.1,2001.2 3437.1,2001.2 3462.1,2002.16 3489.1,2002.16 3516.1,2002.16 2686.81,2004.2 2706.44,2004.12 4090.24,2017.96 4142.32,2021.28 3534.02,2022.2 3063.08,2026.98 2838.98,2031.31 2861.47,2031.31 2883.95,2031.31 2762.6,2039.54 2784.72,2039.54 4162,2040 4214.35,2040 4266.7,2040 4319.05,2040 4371.4,2040 4423.75,2040 4476.1,2040 4528.45,2040 4580.8,2040 4633.15,2040 4685.5,2040 4737.85,2040 4790.2,2040 4842.55,2040 4894.9,2040 4947.25,2040 3144.43,2045.63 3536.47,2050.72 4090.24,2065.44 3535.02,2078.2 2933.87,2078.67 2956.36,2078.67 2978.48,2078.67 4109.92,2084.16 4162.27,2084.16 4214.62,2084.16 4266.97,2084.16 4319.32,2084.16 4371.67,2084.16 4424.02,2084.16 4476.37,2084.16 4528.72,2084.16 4581.07,2084.16 4633.42,2084.16 4685.77,2084.16 4738.12,2084.16 4790.47,2084.16 4842.82,2084.16 4895.17,2084.16 4947.52,2084.16 3381.06,2094.24 3408.06,2094.24 3435.06,2094.24 3460.06,2095.2 3487.06,2095.2 3514.06,2095.2 3038.65,2128.94 3061.13,2128.94 4321.15,2171.47 4918.27,2171.47 3140.52,2182.29 3163,2182.29 3185.13,2182.29 3383.1,2447.06 3410.1,2447.06 3437.1,2447.06 3462.1,2448.02 3489.1,2448.02 3516.1,2448.02 3534.02,2468.06 3536.47,2496.58 3535.02,2524.06 3381.06,2540.1 3408.06,2540.1 3435.06,2540.1 3460.06,2541.06 3487.06,2541.06 3514.06,2541.06
  other v2: 4218.73,1510 4258.73,1510 4298.73,1510 4785,1510 4825,1510 4865,1510 4905,1510 4218.73,1550 4785,1550 4825,1550 4865,1550 4905,1550 4218.73,1590 4785,1590 4825,1590 4865,1590 4905,1590 4785,1630 4825,1630 4865,1630 4905,1630 4785,1670 4825,1670 4865,1670 4905,1670 4785,1710 4825,1710 4865,1710 4905,1710 4785,1760 4825,1760 4865,1760 4905,1760 4785,1800 4825,1800 4865,1800 4905,1800 4785,1840 4825,1840 4865,1840 4905,1840 4218.73,1880 4785,1880 4825,1880 4865,1880 4905,1880 4218.73,1920 4785,1920 4825,1920 4865,1920 4905,1920 4218.73,1960 4258.73,1960 4298.73,1960 4785,1960 4825,1960 4865,1960 4905,1960
pads on no net: FID1.1 FID2.1 FID3.1 FID4.1 FID5.1 FID6.1 H1.1 H2.1 H3.1 H4.1 J1.1 J1.2 J1.3 J1.4 J1.5 J1.7 J1.8 LBL1.0 SH-JP1.0 SH-JP2.0 SH-JP3.0 SH-JP4.0 SH-JP5.0 SH-JP6.0 SH-JP7.0
copper on no net: | length 1021.4
  Bottom Layer w40: 2094.98,2340.79 cw(c2014.41,2353.54) 2095.26,2342.65 ; 3079.24,1033.7 cw(c2998.66,1046.46) 3079.51,1035.56
  other v7: 2998.66,1046.46 2014.41,2353.54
